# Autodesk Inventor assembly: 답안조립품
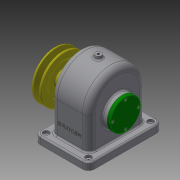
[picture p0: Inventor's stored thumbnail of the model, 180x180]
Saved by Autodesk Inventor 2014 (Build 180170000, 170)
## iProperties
Created: 2016-10
Part Number: 답안조립품
Document SubType Name: Assembly
Designer: USER
Author: USER
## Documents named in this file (15)
- C:\Users\USER\Desktop\461008V1015\답안조립품.iam
- C:\Users\USER\Desktop\461008V1015\본체.ipt
- C:\Users\USER\Desktop\461008V1015\베어링 6203.ipt
- C:\Users\USER\Desktop\461008V1015\축.ipt
- C:\Users\USER\Desktop\461008V1015\키 - 6 x 6 x 22.ipt
- C:\Users\USER\Desktop\461008V1015\스퍼기어.ipt
- C:\Users\USER\Desktop\461008V1015\뒤커버.ipt
- C:\Users\USER\Desktop\461008V1015\앞커버.ipt
- C:\Users\USER\Desktop\461008V1015\오일씰 28 40 8.ipt
- C:\Users\USER\Desktop\461008V1015\부시.ipt
- C:\Users\USER\Desktop\461008V1015\V-벨트풀리.ipt
- C:\Users\USER\Desktop\461008V1015\키 - 5 x 5 x 18.ipt
- C:\Users\USER\Desktop\461008V1015\멈춤나사 - M4x10.ipt
- C:\Users\USER\Desktop\461008V1015\볼트 M3 x 8.ipt
- C:\Users\USER\Desktop\461008V1015\볼트 M3 x 10.ipt
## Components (9 placed, 3 different names)
1. V-벨트풀리:1
2. ISO 4762 M3 x 8:1 — 각도:1
3. ISO 4762 M3 x 8:2
4. ISO 4762 M3 x 8:3
5. ISO 4762 M3 x 8:4
6. ISO 4762 M3 x 10:1 — 각도:2
7. ISO 4762 M3 x 10:2
8. ISO 4762 M3 x 10:3
9. ISO 4762 M3 x 10:4
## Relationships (2: Angle 2)
- 각도:1 [Angle]: ISO 4762 M3 x 8:1
- 각도:2 [Angle]: ISO 4762 M3 x 10:1
